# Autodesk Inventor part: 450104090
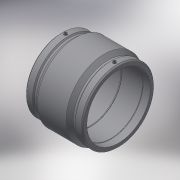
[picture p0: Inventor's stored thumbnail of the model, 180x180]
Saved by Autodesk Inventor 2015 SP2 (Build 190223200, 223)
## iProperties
Created: 2017-06
Part Number: 450104090
Material: Generic
Description: PLASSON COUPLER 90 PN25
Document SubType Name: Modeling
Designer: KIM
Mass: 8622.19 g
Surface Area: 6772.47 cm^2
Volume: 8622.19 cm^3
Density: 1 g/cm^3
Appearance: Default
Author: KIM
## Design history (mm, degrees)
derived "450104.ipt"
feature "Solid1::450104.ipt"
tag "TaggingFeature1"
body "Solid1"
other parameters: "d0" = 148, "d2" = 117, "d3" = 73, "d4" = 37, "d5" = 105.3, "d6" = 72, "d8" = 168 deg, "d10" = 29.2, "d11" = 9.73333, "d13" = 148, "d14" = 17.6296, "d15" = 73, "d16" = 73, "d17" = 89.1, "d19" = 3.52592, "d20" = 168 deg, "d22" = 109.98, "d23" = 117, "d24" = 106.6806, "d25" = 135 deg, "d26" = 66.6, "d27" = 135 deg, "d29" = 69, "d30" = 15, "d31" = 51.8, "d34" = 5 deg, "d35" = 15, "d39" = 5 deg, "d41" = 4, "d42" = 14, "d43" = 0, "d45" = 4, "d46" = 14, "d47" = 0, "d48" = 3, "d49" = 0, "d50" = 3, "d51" = 0, "d52" = 21.17, "d53" = 5.2925, "L_" = 148, "L_1" = 73, "D_" = 117, "A_" = 69, "d_2" = 12
